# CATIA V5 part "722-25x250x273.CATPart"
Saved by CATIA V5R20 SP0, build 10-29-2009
Part number: 722-25x250x273
Definition: NONE
Nomenclature: 722-25x250x273
Source: Unknown
Description: 722-25x250x273
Bounding box of the stored display mesh (mm): x -12.5 to 12.5, y -12.5 to 12.5, z -238 to 35
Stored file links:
  C:\Users\Utente\Desktop\IO LAVORO\3D X SITO CF\X SITO\722\722-25x250x273.CATPart
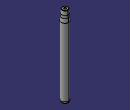
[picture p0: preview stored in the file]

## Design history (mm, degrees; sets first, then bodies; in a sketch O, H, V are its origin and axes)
Body1 "722-25x250x273" (main body)
  Solid1: solid without history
